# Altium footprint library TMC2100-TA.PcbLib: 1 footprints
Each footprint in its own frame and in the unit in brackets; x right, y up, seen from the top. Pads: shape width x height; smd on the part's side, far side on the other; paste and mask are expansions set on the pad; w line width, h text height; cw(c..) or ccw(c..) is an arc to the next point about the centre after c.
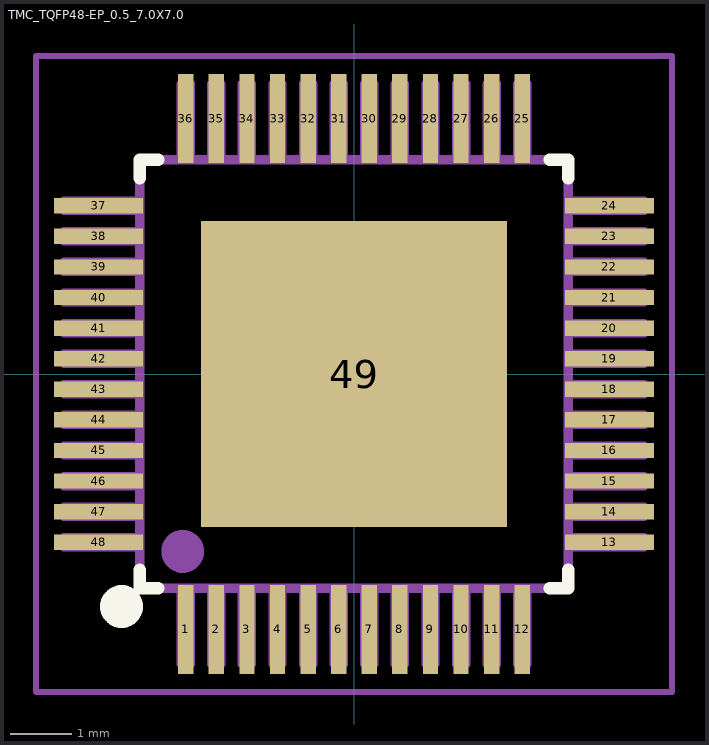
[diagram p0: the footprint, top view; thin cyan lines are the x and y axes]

## TMC_TQFP48-EP_0.5_7.0X7.0 [mm]
pads (49):
  rect 0.25x1.45 smd: 1(-2.75,-4.175) 2(-2.25,-4.175) 3(-1.75,-4.175) 4(-1.25,-4.175) 5(-0.75,-4.175) 6(-0.25,-4.175) 7(0.25,-4.175) 8(0.75,-4.175) 9(1.25,-4.175) 10(1.75,-4.175) 11(2.25,-4.175) 12(2.75,-4.175) 25(2.75,4.175) 26(2.25,4.175) 27(1.75,4.175) 28(1.25,4.175) 29(0.75,4.175) 30(0.25,4.175) 31(-0.25,4.175) 32(-0.75,4.175) 33(-1.25,4.175) 34(-1.75,4.175) 35(-2.25,4.175) 36(-2.75,4.175)
  rect 1.45x0.25 smd: 13(4.175,-2.75) 14(4.175,-2.25) 15(4.175,-1.75) 16(4.175,-1.25) 17(4.175,-0.75) 18(4.175,-0.25) 19(4.175,0.25) 20(4.175,0.75) 21(4.175,1.25) 22(4.175,1.75) 23(4.175,2.25) 24(4.175,2.75) 37(-4.175,2.75) 38(-4.175,2.25) 39(-4.175,1.75) 40(-4.175,1.25) 41(-4.175,0.75) 42(-4.175,0.25) 43(-4.175,-0.25) 44(-4.175,-0.75) 45(-4.175,-1.25) 46(-4.175,-1.75) 47(-4.175,-2.25) 48(-4.175,-2.75)
  rrect0% 5x5 smd paste-254: 49(0,0)
L26-Silk Screen Top (Multiple PADS layers...):
  circle w0.5: c-3.8,-3.8 r0.1
  lines w0.2: -3.5,-3.2 -3.5,-3.5 -3.2,-3.5 ; -3.5,3.2 -3.5,3.5 -3.2,3.5 ; 3.2,-3.5 3.5,-3.5 3.5,-3.2 ; 3.2,3.5 3.5,3.5 3.5,3.2
L23-Paste Mask Top (Multiple PADS layers...):
  region: 0.4,2.4 2.4,2.4 2.4,0.4 0.4,0.4
  region: 0.4,-0.4 2.4,-0.4 2.4,-2.4 0.4,-2.4
  region: -2.4,-0.4 -0.4,-0.4 -0.4,-2.4 -2.4,-2.4
  region: -2.4,2.4 -0.4,2.4 -0.4,0.4 -2.4,0.4
L13:
  drawing of 197 lines, arcs and shapes, not listed
L15 (Multiple PADS layers...):
  lines w0.1: -5.2,-5.2 -5.2,5.2 5.2,5.2 5.2,-5.2 -5.2,-5.2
